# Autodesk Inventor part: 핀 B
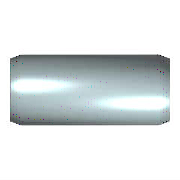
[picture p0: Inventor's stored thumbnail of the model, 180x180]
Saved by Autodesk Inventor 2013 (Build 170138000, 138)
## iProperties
Created: 2012-02
Part Number: 핀 B
Material: 강철, 연강
Description: 평행 핀
Document SubType Name: Modeling
Standard: KS B 1320
Designer: mduedu
Standards Organization: KS
Language: ko-KR
Size Designation: B 4 x  10
Categories: <MemberInstance><Categories><Category DisplayName="조임쇠" InternalName="e4da775c-781d-43d5-af7c-5136215cf5a6" Mnemonic="FSTN"><Category DisplayName="핀" InternalNa
Density: 1 g/cm^3
IsCustomPart: 1
Author: mduedu
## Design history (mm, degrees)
sketch "스케치"
  geometry: C1 r 2 at (0, 0); 1 further point
  constraints: 1 centre point, 1 coincident
  dimensions: "d1" = 4 diameter of C1 (= NND)
extrude "본체" new body sketch "스케치" distance "d2" = 10 (= NLG); taper "d3" = 0 deg
chamfer "스케치2" distance "d8" = 0.63 (= PHH); stored, may be unused: angle "d9" = 15 deg (= FAWI), second distance "d12" = 0.63 (= PHH)
body "Solid1"
chamfer "모따기1" distance "d4" = 0.63 (= PHH); stored, may be unused: angle "d5" = 15 deg (= FAWI), second distance "d11" = 0.63 (= PHH)
other parameters: "NND" = 4 [user parameter; used in 1 equation term], "NLG" = 10 [user parameter; used in 1 equation term], "PHH" = 0.63 [user parameter; used in 4 equation terms], "FAWI" = 15 deg [user parameter; used in 2 equation terms], "d13" = 0, "d15" = 0, "d16" = 0, "KAH" = 0.5 [user parameter]
